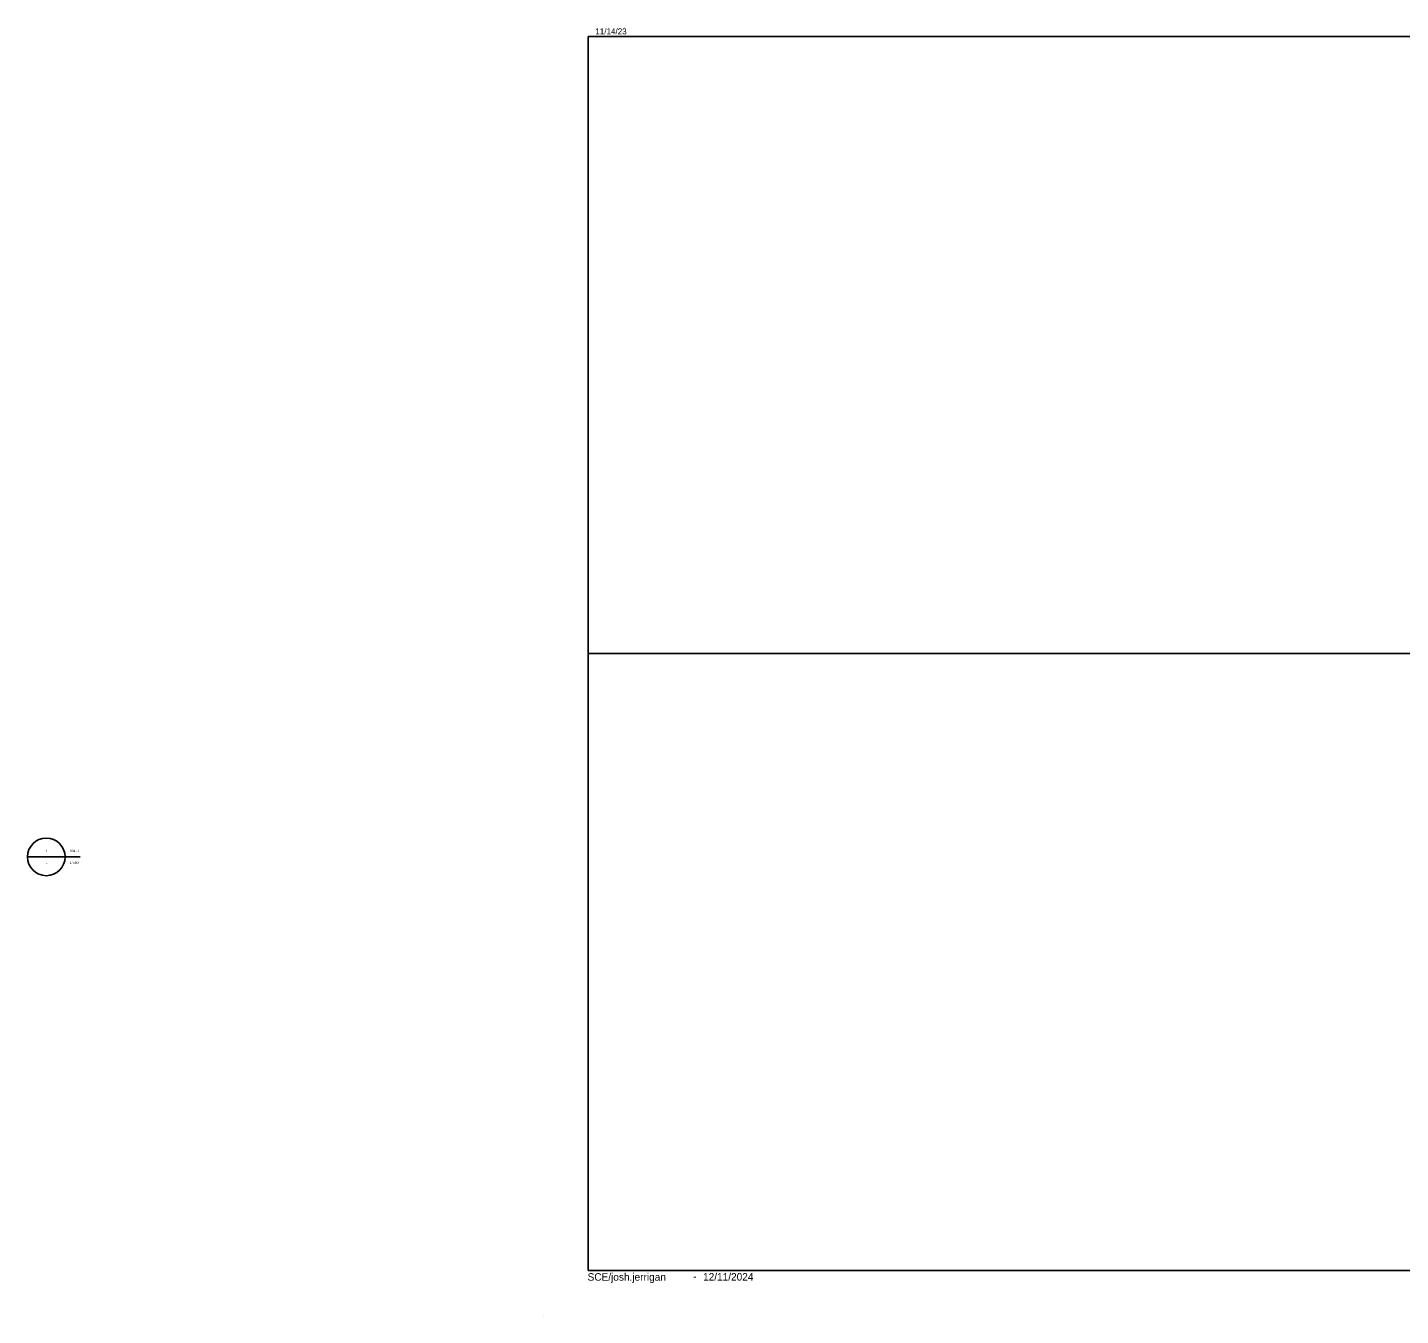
# Model space of a CAD drawing. Extents: x -0.71 to 3.09, y 0 to 1.8.
# Drawn here: x -0.714 to 1.187, y 0 to 1.783 of the extents above; entities that cross this region are included whole.
import ezdxf

# ---------------------------------------------------------------- set-up
doc = ezdxf.new("R2010")
doc.units = 0
for name, color, linetype in [('Default', 7, 'Continuous'), ('P_NCDOT_Horizontal_Alignment_Station_Major_Label', 7, 'Continuous'), ('P_NCDOT_Horizontal_Alignment_Tick_Large', 7, 'Continuous'), ('P_NCDOT_Horizontal_Alignment_Tick_Small', 7, 'Continuous')]:
    doc.layers.add(name, color=color, linetype=linetype)

msp = doc.modelspace()

# ---------------------------------------------------------------- linework, layer by layer
at = {"layer": 'Default'}
for p, q in [((-0.7141, 0.635), (-0.662, 0.635)), ((-0.6878, 0.635), (-0.6411, 0.635))]:
    msp.add_line(p, q, dxfattribs=at)
msp.add_circle((-0.688, 0.635), 0.026, dxfattribs=at)
at = {"layer": 'P_NCDOT_Horizontal_Alignment_Station_Major_Label'}
msp.add_line((0, 0), (0, 0), dxfattribs=at)
at = {"layer": 'P_NCDOT_Horizontal_Alignment_Tick_Large'}
msp.add_line((0.0625, 0.9167), (2.6041, 0.9167), dxfattribs=at)
msp.add_lwpolyline([(0.0625, 0.0625), (2.6041, 0.0625), (2.6041, 1.7708), (0.0625, 1.7708)], close=True, dxfattribs=at)
at = {"layer": 'P_NCDOT_Horizontal_Alignment_Tick_Small'}
for p, q in [((0.0625, 0.0625), (0.0625, 1.7708)), ((2.7708, 1.7708), (0.0625, 1.7708)), ((0.1124, 1.7834), (0.1124, 1.7834)), ((0.0625, 0.0625), (2.7708, 0.0625))]:
    msp.add_line(p, q, dxfattribs=at)

# ---------------------------------------------------------------- texts
at = {"layer": 'Default'}
for s, p in [('1', (-0.6889, 0.6416)), ('L', (-0.689, 0.6252)), ('004 - L', (-0.6553, 0.6416)), ('1"=50\'', (-0.6553, 0.6252))]:
    msp.add_text(s, height=0.00328, dxfattribs=at).set_placement(p)
at = {"layer": 'P_NCDOT_Horizontal_Alignment_Tick_Small'}
msp.add_text('11/14/23', height=0.00833, rotation=0, dxfattribs=at).set_placement((0.0723, 1.7738))
for s, height, p in [('SCE/josh.jerrigan', 0.010417, (0.0616, 0.0482)), ('12/11/2024', 0.01042, (0.2215, 0.0484)), ('-', 0.0104, (0.2078, 0.0492))]:
    msp.add_text(s, height=height, dxfattribs=at).set_placement(p)

doc.saveas('drawing.dxf')
